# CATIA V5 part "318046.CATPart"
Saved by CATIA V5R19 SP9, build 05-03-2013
Part number: 318046
Source: Unknown
Bounding box of the stored display mesh (mm): x -34.399 to 267.6, y -226.99 to -194.518, z 435 to 559
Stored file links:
  D:\16-SIL\kale oto\R19_V1\318046.CATPart
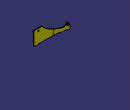
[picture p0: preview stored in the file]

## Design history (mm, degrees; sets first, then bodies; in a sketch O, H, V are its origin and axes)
Body1 "120\\23\\MANIFOLD_SOLID_BREP #40514" (main body)
  Solid1: solid without history
Body2 "241\\222\\MANIFOLD_SOLID_BREP #153170"
  Solid2: solid without history
Body3 "241\\221\\MANIFOLD_SOLID_BREP #154205"
  Solid3: solid without history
